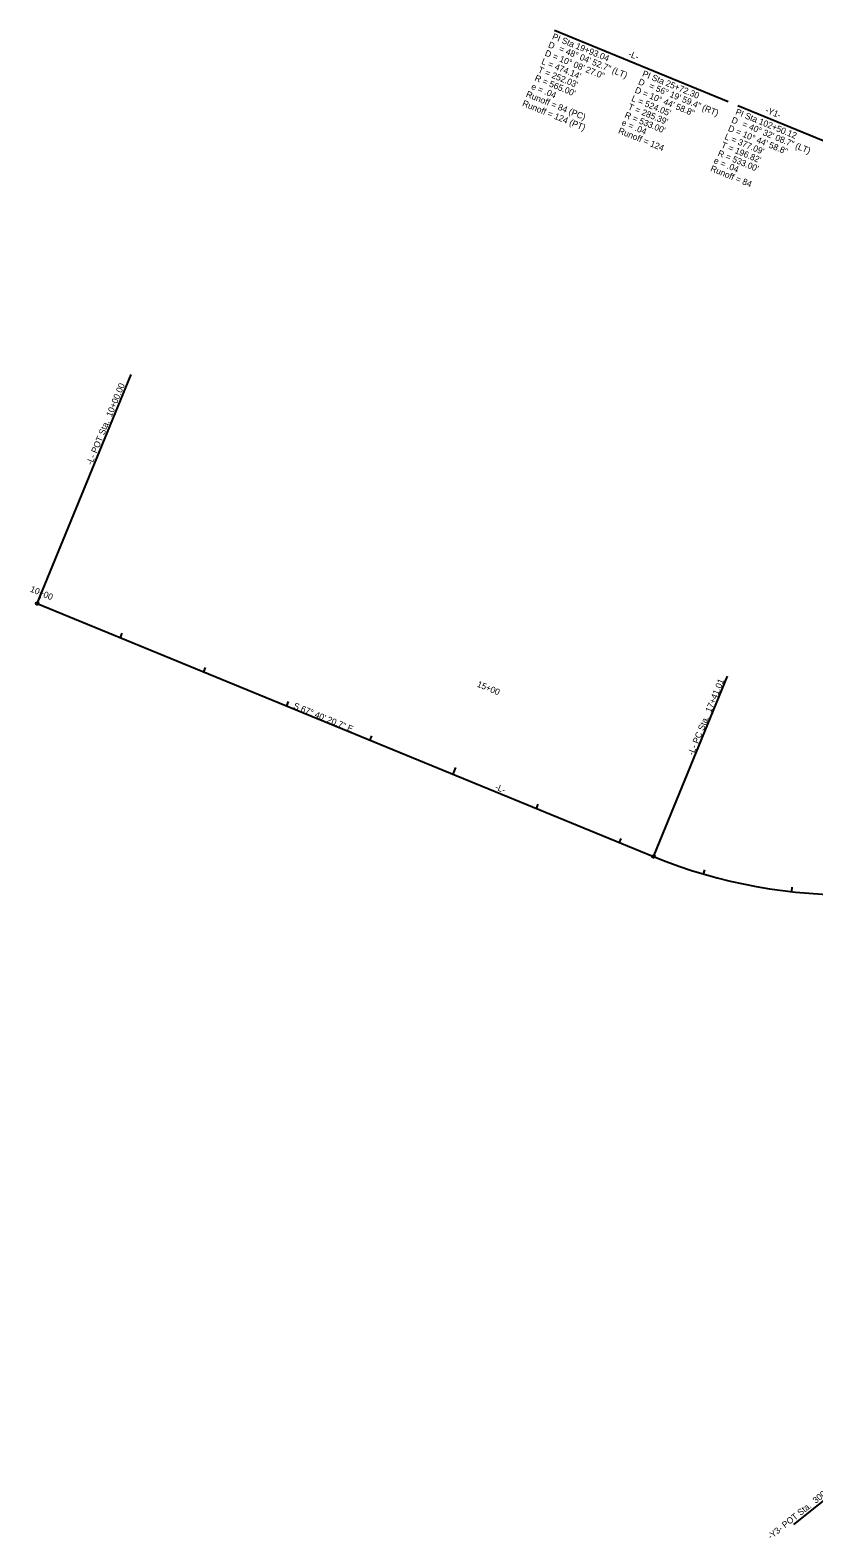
# Model space of a CAD drawing. Extents: x 2090177 to 2092717, y 863117 to 864817.
# Drawn here: x 2090177 to 2091049, y 863141 to 864817 of the extents above; entities that cross this region are included whole.
import ezdxf

# ---------------------------------------------------------------- set-up
doc = ezdxf.new("R2010")
doc.units = 0
for name, color, linetype in [('Prop Horizontal Alignment', 7, 'Continuous'), ('Prop Horizontal Alignment Curve and Spiral Data', 7, 'Continuous'), ('Prop Horizontal Alignment Direction Label', 7, 'Continuous'), ('Prop Horizontal Alignment Point', 7, 'Continuous'), ('Prop Horizontal Alignment Station Label', 7, 'Continuous'), ('Prop Horizontal Alignment Tick Label', 7, 'Continuous'), ('Prop Horizontal Alignment Tick Large', 7, 'Continuous'), ('Prop Horizontal Alignment Tick Small', 7, 'Continuous')]:
    doc.layers.add(name, color=color, linetype=linetype)

msp = doc.modelspace()

# ---------------------------------------------------------------- linework, layer by layer
at = {"layer": 'Prop Horizontal Alignment'}
msp.add_line((2090185.1, 864179.9), (2090870.6, 863898.4), dxfattribs=at)
msp.add_arc((2091085.2, 864421.1), 565, 247.6724, 295.7537, dxfattribs=at)
at = {"layer": 'Prop Horizontal Alignment Curve and Spiral Data'}
for p, q in [((2090760.4, 864817.1), (2090953.6, 864737.8)), ((2090964.2, 864733.5), (2091059.1, 864694.5))]:
    msp.add_line(p, q, dxfattribs=at)
at = {"layer": 'Prop Horizontal Alignment Station Label'}
for p, q in [((2090185.1, 864179.9), (2090289.6, 864434.3)), ((2090871.2, 863899.8), (2090952.9, 864098.8))]:
    msp.add_line(p, q, dxfattribs=at)
msp.add_lwpolyline([(2091213, 863211), (2091165.3, 863266.8), (2091026.2, 863155.8)], dxfattribs=at)
for centre in [(2090185.1, 864179.9), (2090870.6, 863898.4)]:
    msp.add_circle(centre, 1.5, dxfattribs=at)
at = {"layer": 'Prop Horizontal Alignment Tick Large'}
for p, q in [((2090185.1, 864179.9), (2090188.2, 864187.3)), ((2090647.7, 863990), (2090650.7, 863997.4))]:
    msp.add_line(p, q, dxfattribs=at)
at = {"layer": 'Prop Horizontal Alignment Tick Small'}
for p, q in [((2090277.7, 864141.9), (2090279.6, 864146.6)), ((2090370.2, 864103.9), (2090372.1, 864108.6)), ((2090462.7, 864066), (2090464.6, 864070.6)), ((2090555.2, 864028), (2090557.1, 864032.6)), ((2090740.2, 863952), (2090742.1, 863956.6)), ((2090832.7, 863914), (2090834.6, 863918.6)), ((2090926.2, 863878.9), (2090927.6, 863883.7)), ((2091024.2, 863859.4), (2091024.7, 863864.3))]:
    msp.add_line(p, q, dxfattribs=at)

# ---------------------------------------------------------------- texts
at = {"layer": 'Prop Horizontal Alignment Curve and Spiral Data'}
for s, rotation, p in [('PI Sta 19+93.04', 337.9114, (2090757.1, 864807.4)), ('D = 10%%d 08\' 27.0"', 337.9114, (2090749, 864789.1)), ('D', 337.9114, (2090752.7, 864798.3)), ('= 48%%d 04\' 52.7" (LT)', 337.9114, (2090764.7, 864793.8)), ("T = 252.03'", 337.9114, (2090741.4, 864770.5)), ("L = 474.14'", 337.9114, (2090745.2, 864779.8)), ('-L-', 338.2396, (2090841.9, 864788.1)), ("R = 565.00'", 337.9114, (2090737.7, 864761.3)), ('D', 337.7261, (2090852.9, 864757.2)), ('PI Sta 25+72.30', 337.7261, (2090857.3, 864766.2)), ('Runoff = 84 (PC)', 337.9114, (2090728, 864743.4)), ('e = .04', 337.9114, (2090733.8, 864751.9)), ("L = 524.05'", 337.7261, (2090845.3, 864738.7)), ('D = 10%%d 44\' 58.8"', 337.7261, (2090849.1, 864748)), ('= 56%%d 19\' 59.4" (RT)', 337.7261, (2090864.9, 864752.6)), ('Runoff = 124 (PT)', 337.9114, (2090723.9, 864733.2)), ("R = 533.00'", 337.7261, (2090837.7, 864720.2)), ("T = 285.39'", 337.7261, (2090841.5, 864729.4)), ('PI Sta 102+50.12', 337.6724, (2090960.9, 864723.7)), ('-Y1-', 338.2396, (2090994.2, 864725.6)), ('e = .04', 337.7261, (2090834.3, 864711.7)), ('D = 10%%d 44\' 58.8"', 337.6724, (2090952.7, 864705.4)), ('D', 337.6724, (2090956.5, 864714.7)), ('= 40%%d 32\' 08.7" (LT)', 337.6724, (2090968.5, 864710.1)), ('Runoff = 124', 337.7261, (2090830.6, 864702.8)), ("T = 196.82'", 337.6724, (2090945.1, 864686.9)), ("L = 377.09'", 337.6724, (2090948.9, 864696.2)), ("R = 533.00'", 337.6724, (2090941.3, 864677.7)), ('Runoff = 84', 337.7261, (2090933.1, 864660.7)), ('e = .04', 337.7261, (2090936.8, 864669.6))]:
    msp.add_text(s, height=7, rotation=rotation, dxfattribs=at).set_placement(p)
at = {"layer": 'Prop Horizontal Alignment Direction Label'}
msp.add_text('S 67%%d 40\' 20.7" E', height=7, rotation=337.6724, dxfattribs=at).set_placement((2090469.3, 864063.4))
at = {"layer": 'Prop Horizontal Alignment Point'}
msp.add_text('-L-', height=7, rotation=337.6724, dxfattribs=at).set_placement((2090693.6, 863973.1))
at = {"layer": 'Prop Horizontal Alignment Station Label'}
for s, rotation, p in [('-L- POT Sta.  10+00.00', 67.6724, (2090245.9, 864333.2)), ('-L- PC Sta.  17+41.01', 67.6724, (2090914.8, 864010.3)), ('-Y3- POT Sta.  300+00.00', 38.567, (2091000.9, 863138.9))]:
    msp.add_text(s, height=7, rotation=rotation, dxfattribs=at).set_placement(p)
at = {"layer": 'Prop Horizontal Alignment Tick Label'}
for s, p in [('10+00', (2090176.5, 864193.2)), ('15+00', (2090673.5, 864087.5))]:
    msp.add_text(s, height=7, rotation=337.6724, dxfattribs=at).set_placement(p)

doc.saveas('drawing.dxf')
